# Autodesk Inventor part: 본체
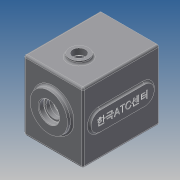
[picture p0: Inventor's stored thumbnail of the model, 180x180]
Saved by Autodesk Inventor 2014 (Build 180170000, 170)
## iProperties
Created: 2016-02
Part Number: 본체
Material: 알루미늄 6061
Document SubType Name: Modeling
Designer: mduedu
Density: 1 g/cm^3
Appearance: 기본값
Mass: 559.381 g
Surface Area: 1077.08 cm^2
Volume: 559.381 cm^3
Author: mduedu
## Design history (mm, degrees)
sketch "스케치1"
  geometry: L1 (-47, -47)-(47, -47); L2 (47, -47)-(47, 63); L3 (47, 63)-(-47, 63); L4 (-47, 63)-(-47, -47); 2 further points
  constraints: 8 end point, 2 parallel, 1 horizontal, 1 midpoint, 1 perpendicular, 1 vertical alignment
  dimensions: "d0" = 94 distance of L2.end L3.end; "d155" = 110 distance of L1.end L2.end; "d156" = 47 distance from line of L1 point (0, 0)
extrude "돌출1" new body sketch "스케치1" distance "d2" = 120; taper "d3" = 0 deg
sketch "스케치3"
  geometry: L1 (47, -47)-(-47, -47) reference; L2 (47, 63)-(47, -47) reference; L3 (-47, 63)-(47, 63) reference; L4 (-47, -47)-(-47, 63) reference; L5 (37, 53)-(37, -37); L6 (37, -37)-(-37, -37); L7 (-37, -37)-(-37, 53); L8 (-37, 53)-(37, 53); 1 further point
  constraints: 8 end point, 3 other
  dimensions: "d226" = 10 distance between parallel lines of L8 L3
extrude "돌출3" cut sketch "스케치3" distance "d11" = 110; taper "d12" = 0 deg
sketch "스케치4"
  geometry: C1 r 21 at (0, 11); 1 further point
  constraints: 1 centre point, 1 vertical alignment
  dimensions: "d13" = 21 radius of C1; "d227" = 11 distance of point (0, 0) C1.centre
extrude "돌출4" join sketch "스케치4" distance "d16" = 7; taper "d17" = 0 deg
sketch "스케치5"
  geometry: C1 r 15 at (0, -20); 1 further point
  constraints: 1 centre point, 1 vertical alignment
  dimensions: "d18" = 15 radius of C1; "d20" = 20 distance of point (0, 0) C1.centre
extrude "돌출5" join sketch "스케치5" distance "d21" = 7; taper "d22" = 0 deg
sketch "스케치6"
  geometry: C1 r 30 at (0, 11); A1 r 21 centre (0, 11) between (8.978, -7.984) and (-8.978, -7.984) reference; 1 further point
  constraints: 1 centre point, 1 coincident
  dimensions: "d228" = 60 diameter of C1
extrude "돌출6" join sketch "스케치6" distance "d25" = 7; taper "d26" = -3 deg
hole "구멍1" diameter "d29" = 35; stored, may be unused: countersink angle "d33" = 90 deg, drill point angle "d35" = 0 deg; dims "d27" = 10, "d28" = 10, "d30" = 6, "d31" = 4, "d32" = 2, "d34" = 10
hole "구멍2" diameter "d38" = 22; stored, may be unused: countersink angle "d42" = 90 deg, drill point angle "d44" = 0 deg; dims "d36" = 10, "d37" = 10, "d39" = 6, "d40" = 4, "d41" = 2, "d43" = 7
hole "구멍3" diameter "d47" = 19; stored, may be unused: countersink angle "d51" = 90 deg, drill point angle "d53" = 0 deg; dims "d45" = 10, "d46" = 10, "d48" = 6, "d49" = 4, "d50" = 2, "d52" = 1
hole "구멍4" diameter "d56" = 32; stored, may be unused: countersink angle "d60" = 90 deg, drill point angle "d62" = 0 deg; dims "d57" = 6, "d58" = 4, "d59" = 2, "d61" = 8, "d220" = 10, "d221" = 10
hole "구멍5" diameter "d65" = 25; stored, may be unused: countersink angle "d69" = 90 deg, drill point angle "d71" = 0 deg; dims "d63" = 10, "d64" = 10, "d66" = 6, "d67" = 4, "d68" = 2, "d70" = 8
fillet "모깎기2" dims "d73" = 0.3
fillet "모깎기3" dims "d74" = 2
chamfer "모따기1" distance "d75" = 1; stored, may be unused: second distance "d76" = 2, angle "d77" = 45 deg
fillet "모깎기4" dims "d78" = 3
fillet "모깎기23" dims "d240" = 1
fillet "모깎기20" dims "d229" = 3
sketch "스케치23"
  geometry: L1 (-37, 53)-(37, 53) reference; L2 (37, 53)-(37, -37) reference; L3 (37, -37)-(-37, -37) reference; L4 (-37, -37)-(-37, 53) reference; L5 (44, -47)-(-44, -47) reference; L6 (47, 60)-(47, -44) reference; L7 (-44, 63)-(44, 63) reference; L8 (-47, -44)-(-47, 60) reference; C1 r 10 at (-37, 53); C2 r 10 at (37, 53); C3 r 10 at (-37, -37); C4 r 10 at (37, -37); A1 r 3 centre (-44, -44) between (-47, -44) and (-44, -47) reference; A2 r 3 centre (44, -44) between (44, -47) and (47, -44) reference; A3 r 3 centre (44, 60) between (47, 60) and (44, 63) reference; A4 r 3 centre (-44, 60) between (-44, 63) and (-47, 60) reference; 1 further point
  constraints: 4 centre point, 4 coincident, 3 equal radius
  dimensions: "d230" = 20 diameter of C1
extrude "돌출22" join sketch "스케치23" stored distance "d235" = 10; taper "d236" = 0 deg
fillet "모깎기21" dims "d237" = 3
node "작업 평면1"
fillet "모깎기22" dims "d239" = 1
sketch "스케치12"
  geometry: A1 r 10 centre (-37, 53) between (-34.692, 43.27) and (-27.27, 50.692) reference; A2 r 10 centre (37, 53) between (27.27, 50.692) and (34.692, 43.27) reference; A3 r 10 centre (37, -37) between (34.692, -27.27) and (27.27, -34.692) reference; A4 r 10 centre (-37, -37) between (-27.27, -34.692) and (-34.692, -27.27) reference; 5 further points
  constraints: 4 coincident
hole "구멍6" sketch "스케치12" at (-37, 53), (37, 53), (37, -37), (-37, -37) diameter "d122" = 3.242; stored, may be unused: countersink angle "d126" = 90 deg, drill point angle "d128" = 120 deg; dims "d123" = 7, "d124" = 4, "d125" = 2, "d127" = 9
sketch "스케치20"
  geometry: L1 (44, 0)-(-44, 0) reference; L2 (44, -120)-(-44, -120) reference; L3 (0, 0)-(0, -120); L4 (-44, -120)-(-44, 0) reference; L5 (44, 0)-(44, -120) reference; C1 r 10 at (0, -79)
  constraints: 2 end point, 1 centre point, 1 midpoint, 1 point on line
  dimensions: "d189" = 20 diameter of C1; "d190" = 41 distance from line of C1.centre L2
extrude "돌출19" cut sketch "스케치20" stored distance "d191" = 10; taper "d192" = 0 deg
sketch "스케치18"
  geometry: C1 r 15 at (0, -79); C2 r 10 at (0, -79) reference; 1 further point
  constraints: 1 centre point, 1 concentric
  dimensions: "d174" = 30 diameter of C1
extrude "돌출17" join sketch "스케치18" distance "d175" = 5; taper "d176" = 0 deg
fillet "모깎기16" dims "d177" = 3
sketch "스케치19"
  geometry: C1 r 15 at (24.351, 79); C2 r 10 at (24.351, 79) reference; 1 further point
  constraints: 1 centre point, 1 concentric
  dimensions: "d178" = 30 diameter of C1
extrude "돌출18" cut sketch "스케치19" distance "d181" = 5; taper "d182" = 0 deg
chamfer "모따기5" distance "d183" = 1; stored, may be unused: second distance "d184" = 2, angle "d185" = 45 deg
fillet "모깎기24" dims "d242" = 3, "d243" = 3
sketch "스케치24"
  geometry: L1 (-95, 67)-(-25, 67); L2 (-25, 67)-(-25, 37); L3 (-25, 37)-(-95, 37); L4 (-95, 37)-(-95, 67); L5 (0, 0)-(0, 104) reference; L6 (-95, 52)-(-25, 52); L7 (-60, 67)-(-60, 37); A1 r 15 centre (-95, 52) between (-95, 37) and (-95, 67); A2 r 15 centre (-25, 52) between (-25, 67) and (-25, 37); A3 r 15 centre (-25, 52) between (-25, 37) and (-25, 67); A4 r 15 centre (-95, 52) between (-95, 67) and (-95, 37); 2 further points
  constraints: 12 end point, 8 point on circle, 5 midpoint, 4 centre point, 2 parallel, 2 perpendicular, 1 horizontal, 1 horizontal alignment
  dimensions: "d244" = 60 distance between parallel lines of L7 L5; "d245" = 100 dimension on A2 A1; "d246" = 30 distance between parallel lines of L3 L1
extrude "돌출23" join sketch "스케치24" distance "d247" = 3; taper "d248" = 0 deg
fillet "모깎기25" dims "d249" = 3
sketch "스케치25"
  geometry: L1 (-25, 67)-(-95, 67) reference; L2 (-95, 37)-(-25, 37) reference; A1 r 15 centre (-95, 52) between (-95, 67) and (-95, 37) reference; A2 r 15 centre (-25, 52) between (-25, 37) and (-25, 67) reference; 3 further points
  constraints: 1 horizontal alignment, 1 midpoint, 1 vertical alignment, 1 other
feature "엠보싱3" sketch "스케치25" dims "d250" = 0.5, "d251" = 0
sketch "스케치26"
  geometry: L1 (14.367, 127)-(73.633, 127) reference; L2 (0, 0)-(88, 0) reference; L3 (88, 120)-(0, 120) reference; 5 further points
  constraints: 3 vertical alignment, 2 midpoint
  dimensions: "d252" = 35 distance from line of point (44, 35) L2; "d253" = 35 distance from line of point (44, 85) L3; "d254" = 50 distance of point (44, 35) point (44, 85) (derived)
hole "구멍8" sketch "스케치26" at (44, 85), (44, 35) diameter "d255" = 6.647; stored, may be unused: countersink angle "d259" = 90 deg, drill point angle "d261" = 118 deg; dims "d256" = 6, "d257" = 4, "d258" = 2, "d260" = 8
node "솔리드1"
node "투영된 루프1"
node "투영된 루프4"
node "투영된 루프5"
node "투영된 루프6"
